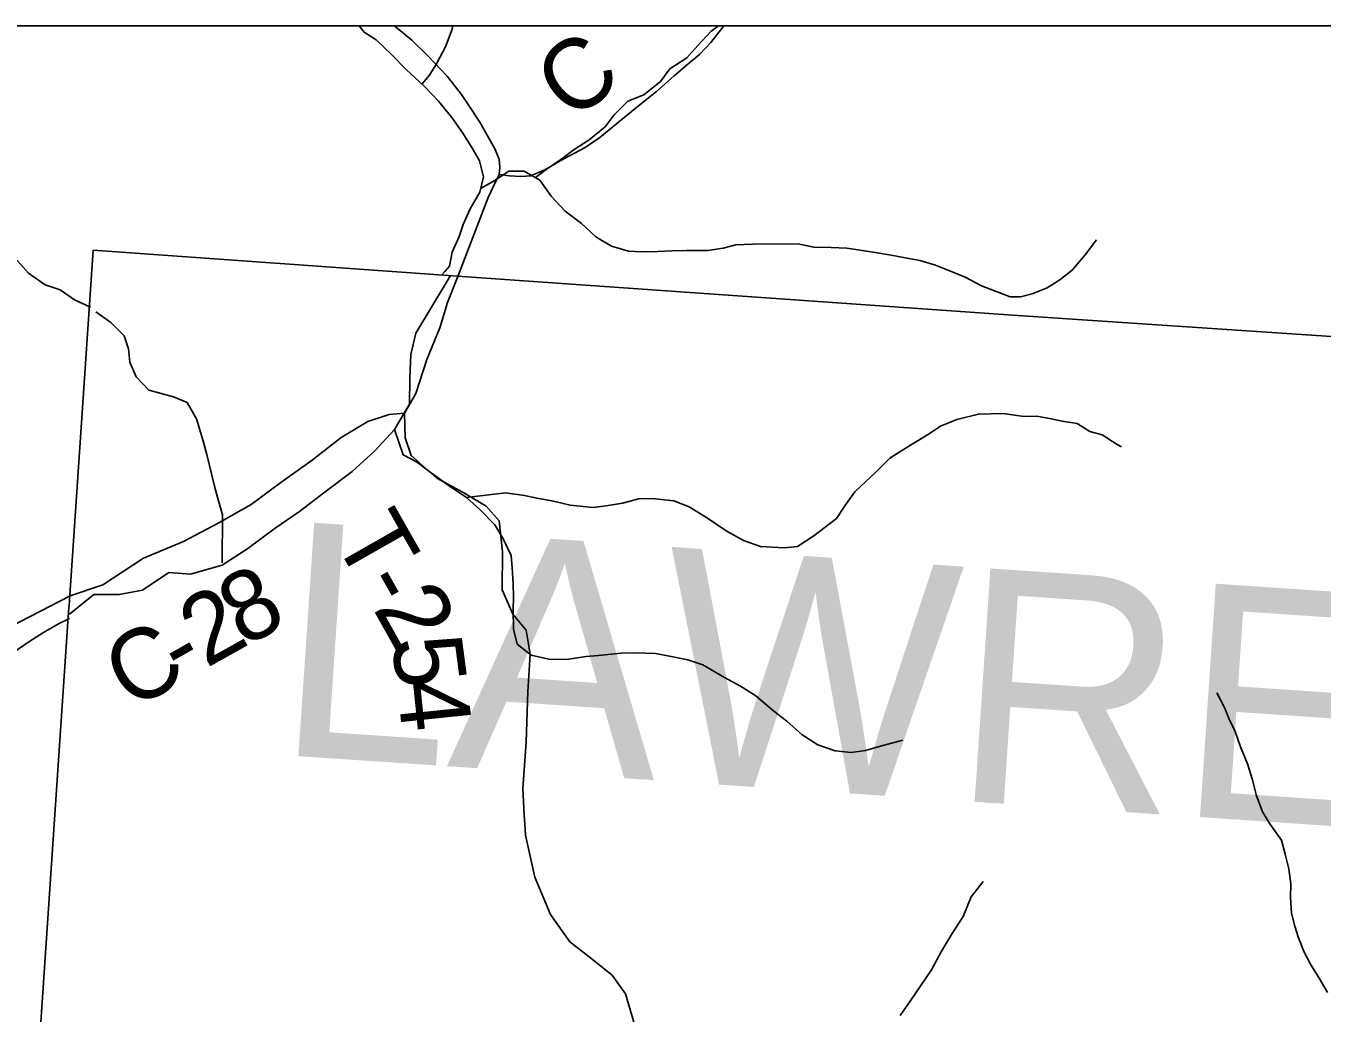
# Model space of a CAD drawing. Extents: x 0 to 44, y -23.8 to 22.
# Drawn here: x 3.565 to 4.614, y 20.101 to 20.9 of the extents above; entities that cross this region are included whole.
import ezdxf

# ---------------------------------------------------------------- set-up
doc = ezdxf.new("R2010")
doc.units = 0
for name, color, linetype in [('Default', 7, 'Continuous'), ('GM_X_County_Road', 7, 'Continuous'), ('GM_X_County_Road_Text', 7, 'Continuous'), ('GM_X_County_Text', 7, 'Continuous'), ('GM_X_Minor_River', 7, 'Continuous'), ('GM_X_Township_Road', 7, 'Continuous'), ('GM_X_Township_Road_Text', 7, 'Continuous'), ('SH_Cut_Line', 7, 'Continuous')]:
    doc.layers.add(name, color=color, linetype=linetype)

msp = doc.modelspace()

# ---------------------------------------------------------------- linework, layer by layer
at = {"layer": 'Default'}
msp.add_lwpolyline([(6.8158, 20.9), (2.3497, 20.9), (2.472, 20.6113), (2.8013, 19.8369), (3.0092, 19.3427), (3.0496, 19.2474), (3.1321, 19.0527), (3.1789, 18.9421), (3.455, 18.29), (3.5135, 19.1552), (3.5139, 19.1608), (3.5639, 19.9016), (3.5995, 20.4294), (3.5996, 20.4304), (3.6002, 20.4391), (3.6191, 20.7184), (3.9141, 20.6975), (4.3639, 20.6657), (6.7023, 20.5094), (6.7107, 20.5383)], close=True, dxfattribs=at)
msp.add_lwpolyline([(7.4495, 20.4611), (7.016, 20.4891), (6.892, 20.4972), (6.8124, 20.5023), (6.7257, 20.5079), (6.7023, 20.5094), (4.3639, 20.6657), (3.9141, 20.6975), (3.6191, 20.7184), (3.6002, 20.4391), (3.5996, 20.4304), (3.5995, 20.4294), (3.5639, 19.9016), (3.5139, 19.1608), (3.5135, 19.1552), (3.455, 18.29), (3.763, 17.5087), (3.7907, 17.4383), (4.026, 16.9163), (4.1422, 16.6361), (4.3476, 16.1408)], dxfattribs=at)
at = {"layer": 'GM_X_County_Road'}
for points in [[(3.9436, 20.7707), (3.948, 20.7797), (3.9484, 20.7854), (3.9478, 20.7921), (3.9444, 20.8006), (3.9323, 20.8222), (3.9227, 20.8364), (3.9174, 20.8444), (3.9059, 20.8593), (3.89, 20.8758), (3.8772, 20.8884), (3.868, 20.8961), (3.8629, 20.9)], [(3.9143, 20.697), (3.939, 20.7611), (3.9436, 20.7707)], [(3.6004, 20.4386), (3.6269, 20.4476), (3.6599, 20.4691), (3.6922, 20.4825), (3.7208, 20.4978), (3.747, 20.5124), (3.7711, 20.5304), (3.7966, 20.5484), (3.8199, 20.5668), (3.8416, 20.5796), (3.8587, 20.5855), (3.8712, 20.5865), (3.8805, 20.6024), (3.8894, 20.63), (3.8999, 20.6557), (3.9061, 20.6762), (3.9143, 20.697)], [(3.5433, 20.4091), (3.6004, 20.4386)]]:
    msp.add_lwpolyline(points, dxfattribs=at)
at = {"layer": 'GM_X_Minor_River'}
for points in [[(3.9011, 20.6981), (3.904, 20.7013), (3.9078, 20.7055), (3.9098, 20.7169), (3.9156, 20.7294), (3.9187, 20.7392), (3.9245, 20.752), (3.9321, 20.7653), (3.9353, 20.7778), (3.932, 20.7907), (3.9267, 20.8002), (3.9185, 20.8132), (3.9095, 20.8258), (3.8987, 20.8391), (3.8874, 20.851), (3.8727, 20.8647), (3.8607, 20.877), (3.8483, 20.8888), (3.8385, 20.895), (3.8344, 20.9)], [(3.8853, 20.8529), (3.8916, 20.86), (3.8974, 20.8698), (3.9043, 20.8831), (3.9097, 20.8974), (3.9105, 20.9)], [(3.9772, 20.7772), (3.986, 20.7838), (3.9986, 20.7924), (4.0085, 20.7999), (4.0207, 20.8078), (4.0336, 20.8183), (4.0409, 20.8281), (4.052, 20.839), (4.0649, 20.8443), (4.0786, 20.8551), (4.0862, 20.8653), (4.0999, 20.8743), (4.1087, 20.8841), (4.1194, 20.8954), (4.1254, 20.9)], [(3.6169, 20.6722), (3.604, 20.6783), (3.5924, 20.6864), (3.5803, 20.6903), (3.5667, 20.6999), (3.5559, 20.7121), (3.5457, 20.7224), (3.533, 20.7362), (3.5247, 20.7461), (3.5142, 20.7587), (3.5056, 20.7717), (3.4936, 20.7831), (3.4857, 20.7953), (3.4851, 20.8075), (3.4852, 20.8204), (3.4849, 20.8306), (3.4861, 20.8412), (3.4869, 20.8533), (3.4878, 20.8659)], [(3.9329, 20.7684), (3.9424, 20.7739), (3.9557, 20.7825), (3.9682, 20.7824), (3.9807, 20.7751), (3.99, 20.7622), (4.0013, 20.7499), (4.0145, 20.74), (4.0261, 20.7292), (4.0389, 20.7216), (4.0525, 20.7177), (4.0631, 20.7172), (4.0764, 20.7175), (4.0881, 20.7178), (4.0995, 20.7181), (4.1169, 20.7183), (4.1294, 20.7201), (4.1396, 20.7227), (4.1529, 20.7233), (4.1672, 20.7236), (4.1911, 20.7234), (4.2028, 20.721), (4.2168, 20.7205), (4.2293, 20.7201), (4.2403, 20.7185), (4.2524, 20.7165), (4.2652, 20.7145), (4.2754, 20.7125), (4.2886, 20.7101), (4.3011, 20.7062), (4.3147, 20.7008), (4.3253, 20.6966), (4.3384, 20.6896), (4.3616, 20.6808)], [(4.3616, 20.6808), (4.3701, 20.6807), (4.3795, 20.683), (4.3917, 20.6879), (4.4019, 20.6943), (4.4118, 20.7022), (4.4225, 20.7147), (4.4316, 20.7268)], [(3.6001, 20.4237), (3.6197, 20.4398), (3.6402, 20.4397), (3.6591, 20.4433), (3.6805, 20.4576), (3.6979, 20.456), (3.7237, 20.4634), (3.7443, 20.4769), (3.7664, 20.4934), (3.7861, 20.507), (3.806, 20.522), (3.8288, 20.5393), (3.8471, 20.5559), (3.8631, 20.5732), (3.8754, 20.5937), (3.8755, 20.6149), (3.8764, 20.6339), (3.8803, 20.6513), (3.9082, 20.6975)], [(3.6212, 20.6685), (3.6334, 20.6599), (3.6442, 20.649), (3.6477, 20.6387), (3.6489, 20.6277), (3.654, 20.616), (3.6643, 20.6051), (3.6841, 20.5996), (3.6952, 20.5951), (3.7029, 20.5819), (3.708, 20.5649), (3.7112, 20.5531), (3.7175, 20.5274), (3.7202, 20.5175), (3.7238, 20.5043), (3.7237, 20.4652)], [(3.9214, 20.5183), (3.9529, 20.522), (3.9684, 20.5199), (3.9783, 20.5177), (3.992, 20.5152), (4.0053, 20.5119), (4.024, 20.5102), (4.0346, 20.5114), (4.0478, 20.5135), (4.0611, 20.517), (4.0717, 20.5175), (4.0892, 20.5154), (4.1018, 20.5106), (4.1167, 20.5016), (4.1316, 20.4911), (4.1457, 20.4833), (4.1594, 20.4785), (4.1788, 20.4775), (4.1894, 20.4784), (4.2026, 20.4872), (4.221, 20.5011), (4.2278, 20.5114), (4.236, 20.5229), (4.2533, 20.539), (4.2642, 20.5501), (4.274, 20.5563), (4.2955, 20.5694), (4.3053, 20.5759), (4.3185, 20.5814), (4.336, 20.5857), (4.3561, 20.5863)], [(4.3561, 20.5863), (4.3728, 20.5837), (4.383, 20.584), (4.3936, 20.5821), (4.4038, 20.5801), (4.4159, 20.5781), (4.4261, 20.5716), (4.4363, 20.5689), (4.4484, 20.5612), (4.4518, 20.5593)], [(3.8631, 20.5732), (3.8702, 20.5528), (3.8809, 20.5472), (3.8927, 20.5382), (3.9084, 20.5269), (3.9214, 20.5183), (3.9321, 20.5086), (3.9444, 20.4961), (3.951, 20.4848), (3.9575, 20.4712), (3.9584, 20.4613), (3.9593, 20.4484), (3.9594, 20.4374), (3.9591, 20.4272), (3.9596, 20.4116), (3.9624, 20.3995), (3.9739, 20.3905), (3.988, 20.3872), (4.0024, 20.387), (4.0183, 20.3894), (4.0282, 20.3902), (4.0468, 20.3923), (4.0589, 20.3924), (4.0745, 20.3918), (4.0885, 20.3893), (4.1007, 20.3868), (4.1129, 20.3827), (4.1304, 20.3726), (4.1434, 20.3655), (4.1556, 20.3577), (4.1702, 20.3453), (4.1809, 20.337), (4.1932, 20.3261), (4.2058, 20.3179), (4.2199, 20.3131), (4.2328, 20.3117), (4.2445, 20.3133), (4.2585, 20.3173), (4.2748, 20.3216)], [(3.5548, 20.3931), (3.567, 20.4014), (3.5788, 20.4089), (3.591, 20.416), (3.5999, 20.4203)], [(4.5289, 20.3601), (4.5352, 20.3483), (4.539, 20.3388), (4.5439, 20.3288), (4.5483, 20.3163), (4.5539, 20.3025), (4.558, 20.2896), (4.561, 20.2774), (4.5659, 20.2637), (4.5719, 20.2541), (4.5813, 20.2408), (4.5843, 20.2294), (4.5872, 20.2176), (4.589, 20.2054), (4.5886, 20.1944), (4.5896, 20.1818), (4.5922, 20.1711), (4.5952, 20.1616), (4.5997, 20.1502), (4.6049, 20.1403), (4.6128, 20.1277), (4.6185, 20.1174)], [(4.3397, 20.2072), (4.33, 20.1949), (4.3237, 20.1789), (4.3147, 20.1652), (4.3057, 20.1503), (4.2979, 20.1358), (4.2807, 20.1105), (4.2725, 20.0987)]]:
    msp.add_lwpolyline(points, dxfattribs=at)
at = {"layer": 'GM_X_Township_Road'}
for points in [[(3.9955, 20.7897), (4.0009, 20.7927), (4.0175, 20.8016), (4.0293, 20.8097), (4.058, 20.8331), (4.0753, 20.847), (4.0895, 20.8595), (4.1007, 20.8691), (4.1102, 20.8768), (4.1193, 20.8865), (4.1291, 20.899), (4.1298, 20.9)], [(3.948, 20.7797), (3.9562, 20.7785), (3.9658, 20.778), (3.9732, 20.7785), (3.9848, 20.7835), (3.9955, 20.7897)], [(3.8712, 20.5865), (3.8718, 20.5664), (3.8766, 20.5523), (3.8973, 20.5339), (3.9192, 20.522), (3.9373, 20.5112), (3.9478, 20.4994), (3.9506, 20.4743), (3.9504, 20.4435), (3.9589, 20.4237), (3.9698, 20.4107), (3.973, 20.3914), (3.9712, 20.361), (3.9698, 20.32), (3.9671, 20.2825), (3.9682, 20.2614), (3.9686, 20.2538)], [(3.9686, 20.2538), (3.9691, 20.2449), (3.9768, 20.2107), (3.9894, 20.1806), (4.0051, 20.1585), (4.0209, 20.1462), (4.0394, 20.1316), (4.0502, 20.1163), (4.0605, 20.0816), (4.0685, 20.0651), (4.0736, 20.0547)]]:
    msp.add_lwpolyline(points, dxfattribs=at)
at = {"layer": 'SH_Cut_Line'}
for points in [[(4.3476, 16.1408), (4.1422, 16.6361), (4.026, 16.9163), (3.7907, 17.4383), (3.763, 17.5087), (3.455, 18.29), (3.5135, 19.1552), (3.5139, 19.1608), (3.5639, 19.9016), (3.5995, 20.4294), (3.5996, 20.4304), (3.6002, 20.4391), (3.6191, 20.7184), (3.9141, 20.6975), (4.3639, 20.6657), (6.7023, 20.5094), (6.7107, 20.5383), (6.8158, 20.9), (2.1, 20.9), (2.1, 14.1)], [(8.9, 20.9), (6.8158, 20.9), (6.7107, 20.5383), (6.7023, 20.5094), (4.3639, 20.6657), (3.9141, 20.6975), (3.6191, 20.7184), (3.6002, 20.4391), (3.5996, 20.4304), (3.5995, 20.4294), (3.5639, 19.9016), (3.5139, 19.1608), (3.5135, 19.1552), (3.455, 18.29), (3.763, 17.5087), (3.7907, 17.4383), (4.026, 16.9163), (4.1422, 16.6361), (4.3476, 16.1408)]]:
    msp.add_lwpolyline(points, dxfattribs=at)

# ---------------------------------------------------------------- texts
at = {"layer": 'GM_X_County_Road_Text'}
for s, rotation, p in [('8', 27.9289, (3.7408, 20.3966)), ('2', 29.2517, (3.7106, 20.3797)), ('C', 29.6246, (3.6498, 20.3452)), ('-', 29.5546, (3.6904, 20.3682))]:
    msp.add_text(s, height=0.0568, rotation=rotation, dxfattribs=at).set_placement(p)
at = {"layer": 'GM_X_County_Text'}
msp.add_text('LAWRENCE COUNTY', height=0.189394, rotation=356.1322, dxfattribs=at).set_placement((3.7646, 20.3102))
at = {"layer": 'GM_X_Township_Road_Text'}
for s, rotation, p in [('C', 38.0752, (4.0066, 20.8214)), ('T', 299.6311, (3.8128, 20.4855)), ('-', 299.6035, (3.8338, 20.4486)), ('2', 299.2634, (3.8453, 20.4284)), ('5', 277.4155, (3.8606, 20.4033)), ('4', 275.9118, (3.8651, 20.3689))]:
    msp.add_text(s, height=0.0568, rotation=rotation, dxfattribs=at).set_placement(p)

doc.saveas('drawing.dxf')
